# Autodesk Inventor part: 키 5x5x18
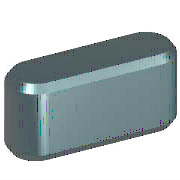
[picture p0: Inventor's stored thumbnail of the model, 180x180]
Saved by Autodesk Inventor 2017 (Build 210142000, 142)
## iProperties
Created: 2012-02
Part Number: 키 5x5x18
Material: 강철, 연강
Description: 키 및 해당 키홈
Document SubType Name: Modeling
Standard: KS B 1311
Designer: mduedu
Standards Organization: KS
Language: ko-KR
Size Designation: 5 x 5 x 18
Categories: <MemberInstance><Categories><Category DisplayName="샤프트 부품" InternalName="7f7aeb1f-a693-4053-b835-cee3144e0d98" Mnemonic="SHFT"><Category DisplayName="키" Interna
Density: 7.86 g/cm^3
Mass: 3.27476 g
Surface Area: 3.57848 cm^2
Volume: 0.416636 cm^3
Appearance: 노란색
IsCustomPart: 1
Author: mduedu
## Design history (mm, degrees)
workplane "Work Plane1"
workplane "Work Plane2"
sketch "스케치1"
  geometry: L1 (2.5, 2.5)-(15.5, 2.5); L2 (15.5, -2.5)-(2.5, -2.5); L3 (0, 9.4)-(0, -7.4) reference; L4 (-5, 0)-(30, 0) reference; L5 (18, 0)-(18, 7); A1 r 2.5 centre (2.5, 0) between (2.5, 2.5) and (2.5, -2.5); A2 r 2.5 centre (15.5, 0) between (15.5, -2.5) and (15.5, 2.5)
  constraints: 6 end point, 5 point on circle, 4 tangent, 3 point on line, 2 centre point, 1 horizontal, 1 parallel, 1 perpendicular
  dimensions: "d0" = 2.5 radius of A1 (= 0.5 x PB); "d13" = 2.5 radius of A2 (= 0.5 x PB); "d14" = 18 distance between parallel lines of L5 L3 (= NLG)
extrude "본체1" new body sketch "스케치1" taper "d3" = 0 deg; stored distance "d4" = 10
workplane "Work Plane3"
body "Solid1"
chamfer "모따기1" distance "d8" = 0.4 (= PHH); stored, may be unused: second distance "d9" = 0.4 (= PHH), angle "d15" = 45 deg
other parameters: "d1" = -3 (= -PNT), "d2" = 2 (= PH - PNT), "NLG" = 18 [user parameter; used in 3 equation terms], "PB" = 5 [user parameter; used in 2 equation terms], "PNT" = 3 [user parameter; used in 2 equation terms], "PH" = 5 [user parameter; used in 1 equation term], "PHH" = 0.4 [user parameter; used in 2 equation terms], "d10" = 0, "d16" = 0, "d17" = 0, "d18" = 0, "WDMIN" = 12 [user parameter], "PLB2" = 18 (= NLG) [user parameter], "WDMAX" = 17 [user parameter], "PLB1" = 18 (= NLG) [user parameter], "RR" = 0.16 [user parameter], "PUEB" = 2.3 [user parameter]
